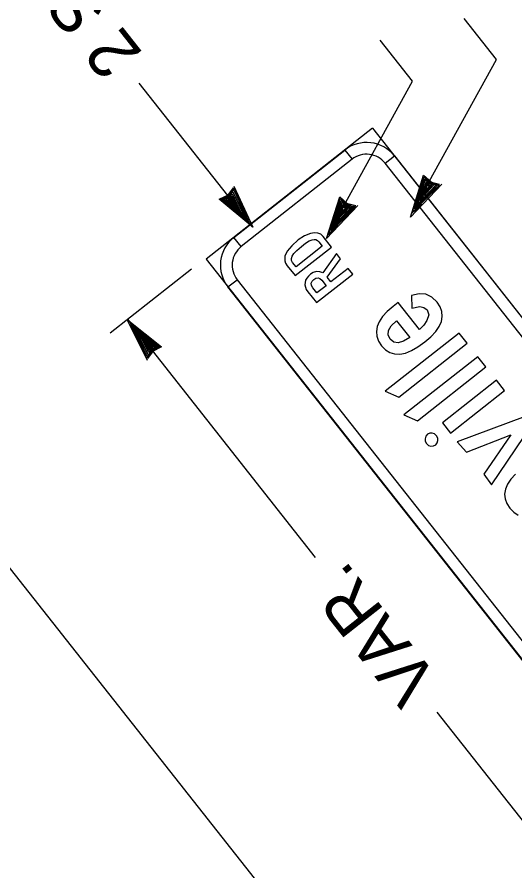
# Model space of a CAD drawing. Extents: x 672126 to 673696, y 1673540 to 1674900.
# Drawn here: x 672217.5 to 672259.8, y 1674609.9 to 1674682.5 of the extents above; entities that cross this region are included whole.
import ezdxf

# ---------------------------------------------------------------- set-up
doc = ezdxf.new("R2010")
doc.units = 0
for name, color, linetype in [('61', 7, 'Continuous'), ('C-ANNO-SYMB', 7, 'Continuous'), ('Level 1', 7, 'Continuous')]:
    doc.layers.add(name, color=color, linetype=linetype)

msp = doc.modelspace()

# ---------------------------------------------------------------- linework, layer by layer
at = {"layer": '61'}
msp.add_lwpolyline([(672259.689, 1674581.406), (672186.159, 1674674.677), (672163.206, 1674656.582), (672236.736, 1674563.312)], close=True, dxfattribs=at)
at = {"layer": 'C-ANNO-SYMB'}
for p, q in [((672247.706, 1674673.092), (672233.571, 1674661.948)), ((672247.706, 1674673.092), (672288.567, 1674621.261)), ((672245.35, 1674671.234), (672245.969, 1674670.449)), ((672248.778, 1674670.117), (672249.564, 1674670.736)), ((672236.546, 1674663.02), (672235.927, 1674663.805)), ((672233.571, 1674661.948), (672274.431, 1674610.117)), ((672235.428, 1674659.592), (672236.213, 1674660.211))]:
    msp.add_line(p, q, dxfattribs=at)
for points in [[(672245.969, 1674670.449), (672236.546, 1674663.02), (672235.927, 1674663.805), (672245.35, 1674671.234), (672245.969, 1674670.449), (672245.969, 1674670.449)], [(672285.924, 1674622.998), (672248.778, 1674670.117), (672249.564, 1674670.736), (672286.71, 1674623.617), (672285.924, 1674622.998), (672285.924, 1674622.998)], [(672236.213, 1674660.211), (672273.359, 1674613.092), (672272.574, 1674612.473), (672235.428, 1674659.592), (672236.213, 1674660.211), (672236.213, 1674660.211)], [(672255.756, 1674654.804), (672255.071, 1674655.674), (672248.788, 1674650.721), (672249.95, 1674650.227)], [(672257.341, 1674652.794), (672256.656, 1674653.664), (672250.373, 1674648.711), (672251.535, 1674648.217)], [(672258.926, 1674650.784), (672258.24, 1674651.653), (672253.65, 1674648.034), (672254.335, 1674647.165)], [(672257.802, 1674642.767), (672261.237, 1674647.852), (672260.664, 1674648.579), (672254.912, 1674646.433), (672255.696, 1674645.551), (672259.462, 1674647.025), (672257.166, 1674643.686)], [(672253.076, 1674646.172), (672253.212, 1674646.33), (672253.267, 1674646.532), (672253.246, 1674646.746), (672253.141, 1674646.939), (672252.975, 1674647.092), (672252.775, 1674647.168), (672252.569, 1674647.161), (672252.375, 1674647.061), (672252.233, 1674646.896), (672252.169, 1674646.69), (672252.19, 1674646.473), (672252.295, 1674646.273), (672252.465, 1674646.124), (672252.673, 1674646.058), (672252.888, 1674646.072)]]:
    msp.add_lwpolyline(points, close=True, dxfattribs=at)
for points in [[(672244.214, 1674662.985), (672243.506, 1674663.882), (672243.306, 1674664.07), (672243.061, 1674664.177), (672242.775, 1674664.203), (672242.443, 1674664.148), (672241.926, 1674663.936), (672241.4, 1674663.587), (672240.842, 1674663.092), (672240.463, 1674662.629), (672240.265, 1674662.201), (672240.246, 1674661.807), (672240.322, 1674661.618), (672240.47, 1674661.398), (672241.133, 1674660.556), (672244.214, 1674662.985)], [(672243.436, 1674663.057), (672241.209, 1674661.301), (672240.924, 1674661.662), (672240.834, 1674661.832), (672240.819, 1674662.018), (672240.881, 1674662.218), (672241.017, 1674662.433), (672241.269, 1674662.697), (672241.673, 1674663.038), (672242.021, 1674663.313), (672242.337, 1674663.508), (672242.578, 1674663.611), (672242.743, 1674663.636), (672242.89, 1674663.615), (672243.022, 1674663.549), (672243.135, 1674663.439), (672243.436, 1674663.057)], [(672246.022, 1674660.692), (672245.641, 1674661.175), (672244.174, 1674660.018), (672243.85, 1674660.43), (672244.999, 1674661.989), (672244.65, 1674662.431), (672243.485, 1674660.786), (672243.226, 1674660.892), (672242.942, 1674660.904), (672242.68, 1674660.831), (672242.432, 1674660.682), (672242.258, 1674660.523), (672242.123, 1674660.353), (672242.029, 1674660.173), (672241.975, 1674659.984), (672241.964, 1674659.781), (672242.001, 1674659.58), (672242.084, 1674659.381), (672242.214, 1674659.185), (672242.941, 1674658.263), (672246.022, 1674660.692)], [(672243.768, 1674659.699), (672242.983, 1674659.08), (672242.627, 1674659.532), (672242.529, 1674659.711), (672242.509, 1674659.901), (672242.57, 1674660.081), (672242.711, 1674660.236), (672242.902, 1674660.347), (672243.079, 1674660.372), (672243.246, 1674660.312), (672243.4, 1674660.166), (672243.768, 1674659.699)], [(672251.693, 1674655.984), (672249.889, 1674658.272), (672249.464, 1674657.937), (672248.964, 1674657.5), (672248.567, 1674657.067), (672248.282, 1674656.641), (672248.102, 1674656.221), (672248.035, 1674655.804), (672248.074, 1674655.394), (672248.225, 1674654.989), (672248.48, 1674654.592), (672248.813, 1674654.252), (672249.18, 1674654.018), (672249.585, 1674653.894), (672250.023, 1674653.881), (672250.503, 1674653.975), (672251.015, 1674654.18), (672251.563, 1674654.493), (672252.15, 1674654.915), (672252.668, 1674655.364), (672253.076, 1674655.805), (672253.374, 1674656.239), (672253.558, 1674656.665), (672253.636, 1674657.084), (672253.598, 1674657.499), (672253.451, 1674657.906), (672253.192, 1674658.305), (672252.747, 1674658.734), (672252.236, 1674658.972), (672251.66, 1674659.02), (672251.014, 1674658.875), (672251.051, 1674657.795), (672251.725, 1674657.923), (672252.081, 1674657.851), (672252.347, 1674657.639), (672252.484, 1674657.236), (672252.327, 1674656.736), (672252.061, 1674656.351), (672251.693, 1674655.984)], [(672250.866, 1674655.293), (672250.349, 1674654.971), (672249.899, 1674654.842), (672249.518, 1674654.906), (672249.205, 1674655.162), (672249.037, 1674655.516), (672249.068, 1674655.896), (672249.304, 1674656.296), (672249.74, 1674656.721), (672250.866, 1674655.293)], [(672259.86, 1674643.679), (672259.463, 1674643.246), (672259.178, 1674642.82), (672258.998, 1674642.4), (672258.932, 1674641.983), (672258.971, 1674641.572), (672259.122, 1674641.168), (672259.376, 1674640.771), (672259.709, 1674640.431), (672260.076, 1674640.197)]]:
    msp.add_lwpolyline(points, dxfattribs=at)
for centre, radius, start, end in [((672247.208, 1674668.879), 3, 38.2506, 128.25081), ((672247.208, 1674668.879), 2, 38.2506, 128.25081), ((672237.784, 1674661.449), 3, 128.25054, 218.25075), ((672237.784, 1674661.449), 2, 128.25054, 218.25075)]:
    msp.add_arc(centre, radius, start, end, dxfattribs=at)
at = {"layer": 'Level 1'}
for p, q in [((672237.554, 1674664.676), (672227.895, 1674676.927)), ((672250.934, 1674665.541), (672252.051, 1674669.091)), ((672251.052, 1674665.839), (672252.087, 1674668.945)), ((672251.28, 1674666.223), (672252.145, 1674668.787)), ((672251.471, 1674666.536), (672252.194, 1674668.665)), ((672252.051, 1674669.091), (672252.69, 1674668.524)), ((672252.087, 1674668.945), (672252.609, 1674668.541)), ((672252.145, 1674668.787), (672252.368, 1674668.595)), ((672252.194, 1674668.665), (672253.081, 1674668.259)), ((672235.414, 1674667.365), (672235.901, 1674668.025)), ((672235.776, 1674667.668), (672235.97, 1674667.979)), ((672235.901, 1674668.025), (672235.833, 1674667.807)), ((672235.922, 1674668.172), (672237.554, 1674664.676)), ((672235.97, 1674667.979), (672237.203, 1674665.104)), ((672253.589, 1674668.34), (672250.934, 1674665.541)), ((672253.22, 1674668.236), (672251.08, 1674665.884)), ((672253.388, 1674668.26), (672251.197, 1674666.028)), ((672251.448, 1674666.395), (672252.281, 1674668.555)), ((672253.081, 1674668.259), (672251.448, 1674666.395)), ((672253.081, 1674668.259), (672251.471, 1674666.536)), ((672251.753, 1674667.009), (672252.281, 1674668.401)), ((672252.893, 1674668.249), (672251.753, 1674667.009)), ((672252.017, 1674667.4), (672252.294, 1674668.27)), ((672252.727, 1674668.228), (672252.017, 1674667.4)), ((672252.331, 1674668.434), (672252.132, 1674667.544)), ((672252.609, 1674668.235), (672252.224, 1674667.796)), ((672252.224, 1674667.796), (672252.35, 1674668.209)), ((672252.281, 1674668.555), (672252.893, 1674668.249)), ((672252.281, 1674668.401), (672252.727, 1674668.228)), ((672252.294, 1674668.27), (672252.609, 1674668.235)), ((672252.779, 1674668.317), (672252.331, 1674668.434)), ((672252.35, 1674668.209), (672252.45, 1674668.178)), ((672252.368, 1674668.595), (672253.081, 1674668.259)), ((672252.45, 1674668.178), (672252.779, 1674668.317)), ((672252.609, 1674668.541), (672253.405, 1674668.342)), ((672252.69, 1674668.524), (672253.027, 1674668.322)), ((672253.027, 1674668.322), (672253.388, 1674668.26)), ((672253.178, 1674668.322), (672253.22, 1674668.236)), ((672234.694, 1674667.057), (672235.461, 1674667.433)), ((672234.842, 1674667.035), (672235.414, 1674667.365)), ((672235.141, 1674667.028), (672235.854, 1674667.694)), ((672235.273, 1674667.162), (672235.854, 1674667.694)), ((672235.276, 1674667.067), (672235.792, 1674667.516)), ((672235.686, 1674667.437), (672235.408, 1674667.067)), ((672235.419, 1674667.008), (672235.749, 1674667.355)), ((672235.461, 1674667.433), (672235.776, 1674667.668)), ((672235.545, 1674666.97), (672235.697, 1674667.248)), ((672235.69, 1674667.079), (672235.686, 1674667.437)), ((672235.697, 1674667.248), (672235.957, 1674666.726)), ((672235.749, 1674667.355), (672236.245, 1674666.384)), ((672235.792, 1674667.516), (672236.506, 1674665.991)), ((672235.833, 1674667.807), (672235.929, 1674667.814)), ((672235.854, 1674667.694), (672236.837, 1674665.55)), ((672235.854, 1674667.694), (672236.959, 1674665.476)), ((672235.929, 1674667.814), (672237.291, 1674664.941)), ((672243.809, 1674663.711), (672244.926, 1674667.261)), ((672244.926, 1674667.261), (672245.566, 1674666.694)), ((672251.932, 1674667.359), (672251.721, 1674666.905)), ((672251.721, 1674666.905), (672252.052, 1674667.255)), ((672252.132, 1674667.544), (672251.932, 1674667.359)), ((672237.554, 1674664.676), (672234.694, 1674667.057)), ((672237.322, 1674664.898), (672234.842, 1674667.035)), ((672235.01, 1674667.029), (672235.273, 1674667.162)), ((672237.054, 1674665.255), (672235.01, 1674667.029)), ((672236.837, 1674665.55), (672235.141, 1674667.028)), ((672236.959, 1674665.476), (672235.276, 1674667.067)), ((672235.408, 1674667.067), (672236.155, 1674666.545)), ((672236.506, 1674665.991), (672235.419, 1674667.008)), ((672236.245, 1674666.384), (672235.545, 1674666.97)), ((672235.623, 1674666.999), (672235.69, 1674667.079)), ((672235.957, 1674666.726), (672235.623, 1674666.999)), ((672236.155, 1674666.545), (672236.25, 1674666.29)), ((672246.464, 1674666.51), (672243.809, 1674663.711)), ((672243.928, 1674664.01), (672244.963, 1674667.116)), ((672244.156, 1674664.393), (672245.021, 1674666.958)), ((672244.324, 1674664.565), (672245.156, 1674666.726)), ((672244.346, 1674664.706), (672245.07, 1674666.836)), ((672244.629, 1674665.179), (672245.157, 1674666.571)), ((672244.963, 1674667.116), (672245.484, 1674666.711)), ((672245.207, 1674666.604), (672245.008, 1674665.715)), ((672245.021, 1674666.958), (672245.243, 1674666.765)), ((672245.07, 1674666.836), (672245.956, 1674666.43)), ((672245.156, 1674666.726), (672245.768, 1674666.42)), ((672245.157, 1674666.571), (672245.602, 1674666.398)), ((672245.655, 1674666.487), (672245.207, 1674666.604)), ((672245.243, 1674666.765), (672245.956, 1674666.43)), ((672245.325, 1674666.348), (672245.655, 1674666.487)), ((672245.484, 1674666.711), (672246.28, 1674666.512)), ((672245.566, 1674666.694), (672245.903, 1674666.492)), ((672245.903, 1674666.492), (672246.264, 1674666.43)), ((672246.053, 1674666.492), (672246.095, 1674666.406)), ((672251.263, 1674665.986), (672251.855, 1674666.671)), ((672251.855, 1674666.671), (672251.28, 1674666.223)), ((672246.095, 1674666.406), (672243.955, 1674664.054)), ((672246.264, 1674666.43), (672244.072, 1674664.198)), ((672245.956, 1674666.43), (672244.324, 1674664.565)), ((672245.956, 1674666.43), (672244.346, 1674664.706)), ((672245.768, 1674666.42), (672244.629, 1674665.179)), ((672244.893, 1674665.57), (672245.169, 1674666.44)), ((672245.602, 1674666.398), (672244.893, 1674665.57)), ((672245.484, 1674666.405), (672245.1, 1674665.966)), ((672245.1, 1674665.966), (672245.225, 1674666.379)), ((672245.169, 1674666.44), (672245.484, 1674666.405)), ((672245.225, 1674666.379), (672245.325, 1674666.348)), ((672244.808, 1674665.53), (672244.596, 1674665.075)), ((672244.596, 1674665.075), (672244.927, 1674665.426)), ((672245.008, 1674665.715), (672244.808, 1674665.53)), ((672244.138, 1674664.157), (672244.731, 1674664.841)), ((672244.731, 1674664.841), (672244.156, 1674664.393)), ((672232.338, 1674661.117), (672225.434, 1674655.675)), ((672228.582, 1674653.351), (672226.878, 1674656.813)), ((672226.878, 1674656.813), (672229.787, 1674654.492)), ((672242.869, 1674636.599), (672226.912, 1674656.84)), ((672227.238, 1674656.392), (672227.114, 1674656.595)), ((672227.114, 1674656.595), (672229.638, 1674654.51)), ((672228.568, 1674653.709), (672227.146, 1674656.553)), ((672227.146, 1674656.553), (672227.175, 1674656.346)), ((672227.175, 1674656.346), (672227.6, 1674655.546)), ((672228.529, 1674653.544), (672227.238, 1674656.392)), ((672227.6, 1674655.546), (672227.39, 1674656.244)), ((672227.39, 1674656.244), (672229.47, 1674654.513)), ((672228.64, 1674653.83), (672227.489, 1674656.025)), ((672227.489, 1674656.025), (672229.205, 1674654.47)), ((672228.64, 1674653.83), (672227.613, 1674655.953)), ((672227.613, 1674655.953), (672229.338, 1674654.511)), ((672228.214, 1674655.226), (672227.867, 1674655.587)), ((672227.867, 1674655.587), (672228.074, 1674655.152)), ((672228.699, 1674654.009), (672227.952, 1674655.52)), ((672227.952, 1674655.52), (672229.06, 1674654.525)), ((672228.315, 1674654.973), (672228.214, 1674655.226)), ((672228.738, 1674654.172), (672228.221, 1674655.132)), ((672228.221, 1674655.132), (672228.933, 1674654.561)), ((672229.073, 1674654.467), (672228.315, 1674654.973)), ((672228.787, 1674654.279), (672228.517, 1674654.797)), ((672228.517, 1674654.797), (672228.856, 1674654.531)), ((672229.073, 1674654.169), (672228.6, 1674653.498)), ((672229.338, 1674654.511), (672228.64, 1674653.83)), ((672229.21, 1674654.375), (672228.64, 1674653.83)), ((672229.205, 1674654.47), (672228.699, 1674654.009)), ((672229.027, 1674654.099), (672228.717, 1674653.858)), ((672229.06, 1674654.525), (672228.738, 1674654.172)), ((672228.933, 1674654.561), (672228.787, 1674654.279)), ((672228.856, 1674654.531), (672228.791, 1674654.448)), ((672228.791, 1674654.448), (672228.802, 1674654.091)), ((672228.802, 1674654.091), (672229.073, 1674654.467)), ((672229.787, 1674654.492), (672229.027, 1674654.099)), ((672229.638, 1674654.51), (672229.073, 1674654.169)), ((672229.47, 1674654.513), (672229.21, 1674654.375)), ((672228.717, 1674653.858), (672228.529, 1674653.544)), ((672228.663, 1674653.718), (672228.568, 1674653.709)), ((672267.807, 1674604.895), (672253.192, 1674623.434))]:
    msp.add_line(p, q, dxfattribs=at)
for points in [[(672252.072, 1674667.748), (672258.234, 1674678.925), (672255.488, 1674682.408)], [(672244.947, 1674665.919), (672251.109, 1674677.095), (672248.364, 1674680.578)]]:
    msp.add_lwpolyline(points, dxfattribs=at)

# ---------------------------------------------------------------- texts
for s, p in [('2 SIGNS REQUIRED', (672228.252, 1674679.465)), ('VAR.', (672253.453, 1674626.153))]:
    msp.add_text(s, height=4.2, rotation=128.25054, dxfattribs=at).set_placement(p)

doc.saveas('drawing.dxf')
